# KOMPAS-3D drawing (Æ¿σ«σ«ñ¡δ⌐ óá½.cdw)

Referenced files: Тихоходный вал.cdw
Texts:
  Вал тихоходный
  Яковлев Д.А.
  Курсовая по деталям машин.
  Noncommercial version
  Ra 0,63
  Ra 2,5
  Rz 40
  Rz 20
  HB 270...300.
  Овальность и конусность поверхн. А, Б не более
  Rz 80
  Сталь 45 ГОСТ 1050-88
  ДГТУ
Dimensions and other numbers on the sheet: 65; 60; 5; 63; 70; 58; 56; 8; 2; 0,4; 2 фаски; 1; 88; 25; 226; 265; 23; 18; 0,15; 0,035; 50; 16; 0,01 мм.; 1:1; 0; 3; 4; 6; 7; 9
